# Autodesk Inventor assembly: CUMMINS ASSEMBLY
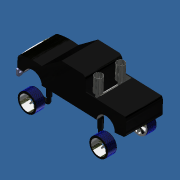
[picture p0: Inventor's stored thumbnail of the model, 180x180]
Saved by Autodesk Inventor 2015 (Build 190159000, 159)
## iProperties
Created: 2014-10
Part Number: CUMMINS ASSEMBLY
Document SubType Name: Assembly
Designer: caovt
Author: caovt
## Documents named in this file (6)
- D:\INVENTOR\TRACTOR TRAILER\CUMMINS ASSEMBLY.iam
- D:\INVENTOR\TRACTOR TRAILER\CUMMINS.ipt
- D:\INVENTOR\TRACTOR TRAILER\CUMMINS TOP OF SHOCK.ipt
- D:\INVENTOR\TRACTOR TRAILER\CUMMINS BOTTOM SHOCK.ipt
- D:\INVENTOR\TRACTOR TRAILER\CUMMINS BOTTOM SHOCK 3.ipt
- D:\INVENTOR\TRACTOR TRAILER\NEW CUMMINS WHEEL.ipt
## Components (13 placed, 5 different names)
1. CUMMINS BOTTOM SHOCK:2 — Insert:2, Insert:19
2. CUMMINS TOP OF SHOCK:1 — Insert:2, Insert:11, Angle:1
3. CUMMINS TOP OF SHOCK:2 — Angle:2, Insert:14, Insert:16
4. CUMMINS BOTTOM SHOCK:3 — Insert:10, Insert:17
5. CUMMINS TOP OF SHOCK:3 — Insert:10, Insert:12
6. CUMMINS TOP OF SHOCK:4 — Angle:3, Insert:13, Insert:15
7. CUMMINS:1 — Insert:11, Angle:1, Insert:12, Angle:2, Angle:3, Insert:13, Angle:4, Angle:5, Insert:16
8. CUMMINS BOTTOM SHOCK 3:1 — Insert:14, Angle:4, Insert:18
9. CUMMINS BOTTOM SHOCK 3:2 — Insert:15, Angle:5, Insert:20
10. NEW CUMMINS WHEEL:1 — Insert:20
11. NEW CUMMINS WHEEL:2 — Insert:19
12. NEW CUMMINS WHEEL:3 — Insert:18
13. NEW CUMMINS WHEEL:4 — Insert:17
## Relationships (17: Insert 12, Angle 5)
- Insert:2: CUMMINS BOTTOM SHOCK:2 ↔ CUMMINS TOP OF SHOCK:1
- Insert:10: CUMMINS BOTTOM SHOCK:3 ↔ CUMMINS TOP OF SHOCK:3
- Insert:11: CUMMINS TOP OF SHOCK:1 ↔ CUMMINS:1
- Angle:1: CUMMINS TOP OF SHOCK:1 ↔ CUMMINS:1
- Insert:12: CUMMINS TOP OF SHOCK:3 ↔ CUMMINS:1
- Angle:2: CUMMINS TOP OF SHOCK:2 ↔ CUMMINS:1
- Angle:3: CUMMINS TOP OF SHOCK:4 ↔ CUMMINS:1
- Insert:13: CUMMINS TOP OF SHOCK:4 ↔ CUMMINS:1
- Insert:14: CUMMINS TOP OF SHOCK:2 ↔ CUMMINS BOTTOM SHOCK 3:1
- Angle:4: CUMMINS:1 ↔ CUMMINS BOTTOM SHOCK 3:1
- Insert:15: CUMMINS TOP OF SHOCK:4 ↔ CUMMINS BOTTOM SHOCK 3:2
- Angle:5: CUMMINS:1 ↔ CUMMINS BOTTOM SHOCK 3:2
- Insert:16: CUMMINS TOP OF SHOCK:2 ↔ CUMMINS:1
- Insert:17: CUMMINS BOTTOM SHOCK:3 ↔ NEW CUMMINS WHEEL:4
- Insert:18: CUMMINS BOTTOM SHOCK 3:1 ↔ NEW CUMMINS WHEEL:3
- Insert:19: CUMMINS BOTTOM SHOCK:2 ↔ NEW CUMMINS WHEEL:2
- Insert:20: CUMMINS BOTTOM SHOCK 3:2 ↔ NEW CUMMINS WHEEL:1
